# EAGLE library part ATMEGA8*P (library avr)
MICROCONTROLLER 8 Kbytes FLASH 1 kbytes SRAM 512 bytes EEPROM USART 4-channel 10 bit ADC 2-channel 8 bit ADC
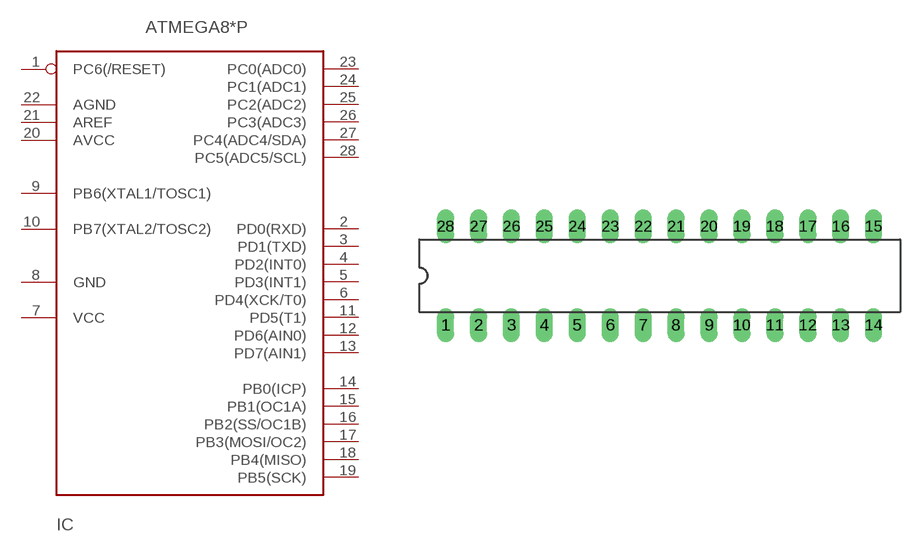
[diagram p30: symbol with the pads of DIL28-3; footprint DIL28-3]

Designator prefix IC

## ATMEGA8-16P, ATMEGA8L-8P  [DIL28-3]
1  PC6(/RESET)
2  PD0(RXD)
3  PD1(TXD)
4  PD2(INT0)
5  PD3(INT1)
6  PD4(XCK/T0)
7  VCC
8  GND
9  PB6(XTAL1/TOSC1)
10  PB7(XTAL2/TOSC2)
11  PD5(T1)
12  PD6(AIN0)
13  PD7(AIN1)
14  PB0(ICP)
15  PB1(OC1A)
16  PB2(SS/OC1B)
17  PB3(MOSI/OC2)
18  PB4(MISO)
19  PB5(SCK)
20  AVCC
21  AREF
22  AGND
23  PC0(ADC0)
24  PC1(ADC1)
25  PC2(ADC2)
26  PC3(ADC3)
27  PC4(ADC4/SDA)
28  PC5(ADC5/SCL)

## Footprint DIL28-3 (pad centres in mm)
Dual In Line 0.3 inch
drill 0.813 long: 1 -16.51,-3.81; 2 -13.97,-3.81; 3 -11.43,-3.81; 4 -8.89,-3.81; 5 -6.35,-3.81; 6 -3.81,-3.81; 7 -1.27,-3.81; 8 1.27,-3.81; 9 3.81,-3.81; 10 6.35,-3.81; 11 8.89,-3.81; 12 11.43,-3.81; 13 13.97,-3.81; 14 16.51,-3.81; 15 16.51,3.81; 16 13.97,3.81; 17 11.43,3.81; 18 8.89,3.81; 19 6.35,3.81; 20 3.81,3.81; 21 1.27,3.81; 22 -1.27,3.81; 23 -3.81,3.81; 24 -6.35,3.81; 25 -8.89,3.81; 26 -11.43,3.81; 27 -13.97,3.81; 28 -16.51,3.81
